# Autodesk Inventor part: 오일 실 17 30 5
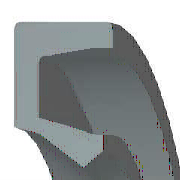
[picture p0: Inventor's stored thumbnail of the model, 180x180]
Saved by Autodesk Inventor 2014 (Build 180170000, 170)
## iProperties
IsCustomPart: 1
Created: 2012-02
Part Number: 오일 실 17 30 5
Material: 고무
Description: 오일 실 - 비스프링, 금속 케이스 GM
Document SubType Name: Modeling
Standard: JIS B 2402
Designer: mduedu
Standards Organization: JIS
Language: ko-KR
Size Designation: 17 30 5 B
Categories: <MemberInstance><Categories><Category DisplayName="샤프트 부품" InternalName="7f7aeb1f-a693-4053-b835-cee3144e0d98" Mnemonic="SHFT"><Category DisplayName="실링" Intern
Density: 0.93 g/cm^3
Appearance: Rubber-Black
Author: mduedu
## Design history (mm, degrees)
body "Solid1"
revolve "회전1" stored, may be unused: angle "d27" = 360 deg
fillet "모깎기1" dims "d28" = 0.25 (= 0.05 x b)
chamfer "모따기1" distance "d29" = 0.07143 (= 0.0142857 x b); stored, may be unused: second distance "d30" = 0.25 (= 0.05 x b), angle "d35" = 45 deg
sketch "스케치2"
  geometry: L1 (-9.367, -3.238)-(-10.233, -3.863); L2 (-8.5, -1.625)-(-9.367, -3.238); L3 (-9.15, -1)-(-8.5, -1.625); L4 (-11.317, -3.75)-(-9.15, -1); L5 (-13.075, -3.75)-(-11.317, -3.75); L6 (-14.375, -1.25)-(-13.075, -3.75); L7 (-14.375, 0)-(-14.375, -1.25); L8 (-15, 0)-(-14.375, 0); L9 (-15, -5)-(-15, 0); L10 (-11.129, -5)-(-15, -5); L11 (-10.233, -3.863)-(-11.129, -5); L12 (0, -9.6)-(0, 1.6) reference; L13 (-14, 0)-(-28, 0) reference
  constraints: 22 end point, 3 horizontal, 2 vertical, 1 parallel
  dimensions: "d2" = 5 distance of L9.start L8.start (= b); "d4" = 1 vertical distance of L8.start L3.start (= 0.2 x b); "d6" = 0.625 distance of L8.start L7.start (= 0.125 x b); "d8" = 1.25 distance of L7.start L6.start (= 0.25 x b); "d10" = 1.25 vertical distance of L5.start L9.start (= 0.25 x b); "d12" = 1.3 horizontal distance of L6.start L5.start (= 0.1 x dd - 0.1 x Diam); "d14" = 1.6129 vertical distance of L2.start L1.start (= 0.322581 x b); "d16" = 0.86667 horizontal distance of L1.start L1.end (= 0.0666667 x dd - 0.0666667 x Diam); "d18" = 0.86667 horizontal distance of L2.start L1.start (= 0.0666667 x dd - 0.0666667 x Diam); "d20" = 0.625 vertical distance of L3.start L2.start (= 0.125 x b); "d22" = 0.65 horizontal distance of L3.start L2.start (= 0.05 x dd - 0.05 x Diam); "d24" = 0.625 vertical distance of L1.start L1.end (= 0.125 x b); "d26" = 2.16667 horizontal distance of L4.start L3.start (= 0.166667 x dd - 0.166667 x Diam); "d31" = 0 distance between parallel lines of L8 L13; "d32" = 15 distance between parallel lines of L12 L9 (= 0.5 x dd); "d33" = 8.5 distance from line of L12 L2.start (= 0.5 x Diam)
other parameters: "Diam" = 17 [user parameter; used in 6 equation terms], "b" = 5 [user parameter; used in 11 equation terms], "d1" = 8 (derived), "d3" = 1.6 (derived), "d5" = 1 (derived), "d7" = 2 (derived), "d9" = 2 (derived), "d11" = 2 (derived), "d13" = 2.58065 (derived), "d15" = 1.33333 (derived), "d17" = 1.33333 (derived), "d19" = 1 (derived), "d21" = 1 (derived), "d23" = 1 (derived), "d25" = 3.33333 (derived), "d34" = 0
